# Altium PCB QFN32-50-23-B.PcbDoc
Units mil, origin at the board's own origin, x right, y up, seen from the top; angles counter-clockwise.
Board outline 1000 x 3400 mil, 2 copper layers (Top Layer, Bottom Layer), stack 11.378 mil thick; 33 components, 20 nets, 122 pads, 512 vias.
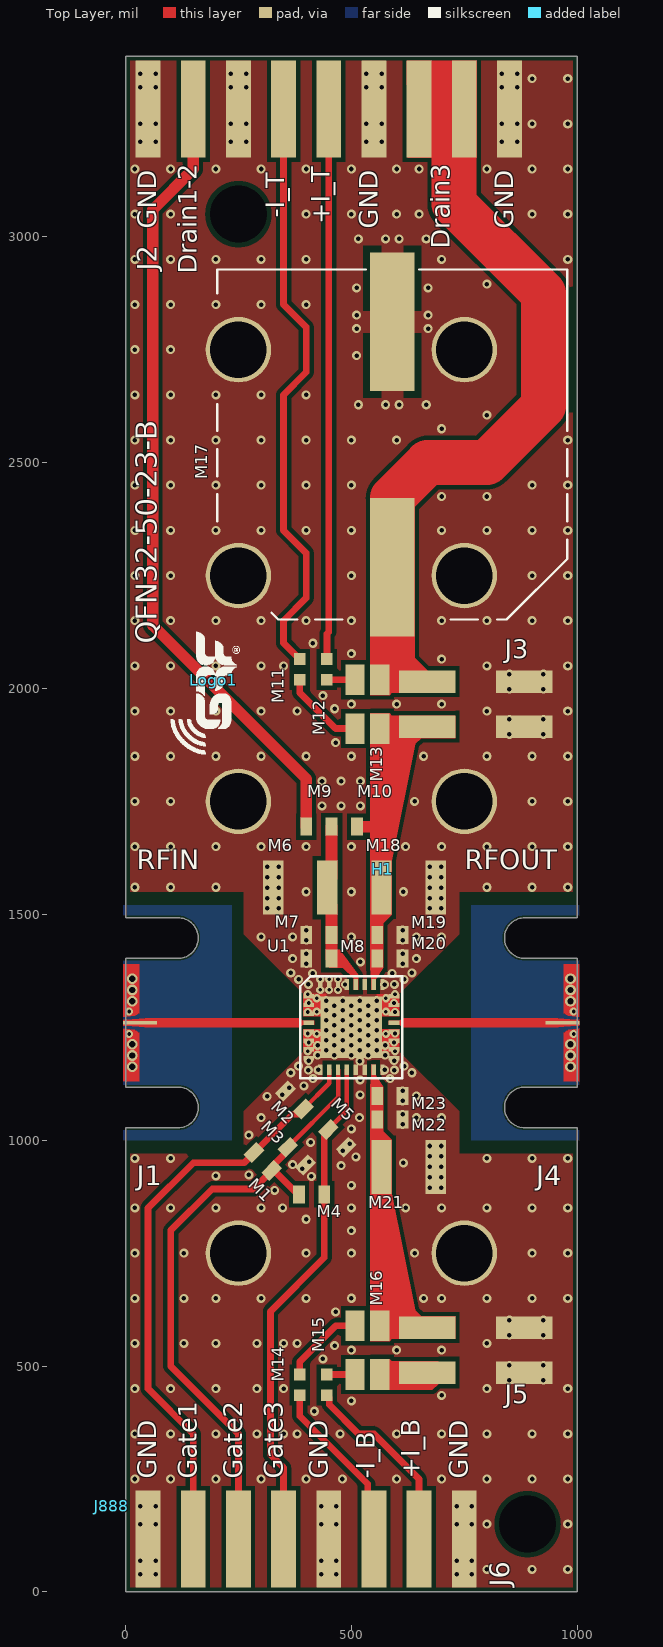
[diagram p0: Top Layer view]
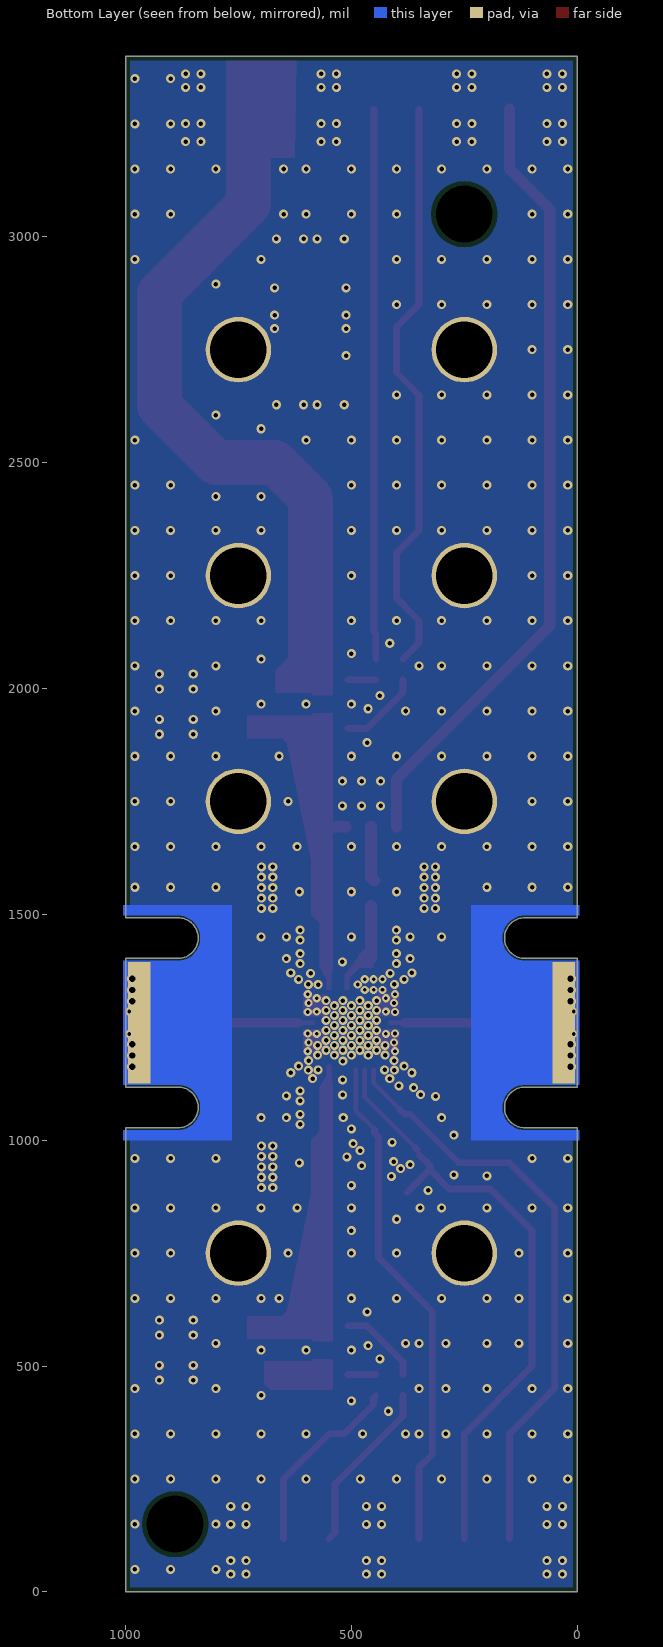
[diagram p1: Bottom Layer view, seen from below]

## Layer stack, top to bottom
Top Layer: signal copper 0.689
Dielectric 1: prepreg 10, RO4350B, Dk 3.48
Bottom Layer: signal copper 0.689

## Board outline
0,0 0,1027.5 116,1027.5 ccw(c116,1072.5) 116,1117.5 0,1117.5 0,1402.5 116,1402.5 ccw(c116,1447.5) 116,1492.5 0,1492.5 0,3400 1000,3400 1000,1492.5 884,1492.5 ccw(c884,1447.5) 884,1402.5 1000,1402.5 1000,1117.5 884,1117.5 ccw(c884,1072.5) 884,1027.5 1000,1027.5 1000,0

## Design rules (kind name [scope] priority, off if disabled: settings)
BackDrilling [IsVia and not InNet('GND')] p1: maxstublength=5 usetopbackdrill=TRUE usebottombackdrill=TRUE holeoversize=10 holetolplus=0.2 holetolminus=0.2
BoardOutlineClearance [All] p1: gap=10 ignorepadtopadclearanceinfootprint=FALSE
Clearance Clearance_I/O [InNetClass('I/O') vs InNet('GND')] p1: gap=7 ignorepadtopadclearanceinfootprint=TRUE
Clearance Clearance_RF_Strip [InNetClass('RF_Strip') vs InNet('GND')] p2: gap=40 ignorepadtopadclearanceinfootprint=TRUE
Clearance Clearance_RF_15-15-8 [InNetClass('RF_15-15-8') vs InNet('GND')] p3: gap=15 ignorepadtopadclearanceinfootprint=TRUE
Clearance Clearance_RF_20-10-12 [InNetClass('RF_20-10-12') vs InNet('GND')] p4: gap=10 ignorepadtopadclearanceinfootprint=TRUE
Clearance Clearance_RF_30-20-16 [InNetClass('RF_30-20-16') vs InNet('GND')] p5: gap=20 ignorepadtopadclearanceinfootprint=TRUE
Clearance Clearance_RF_28-21-16_FR4 [InNetClass('RF_28-21-16_FR4') vs InNet('GND')] p6: gap=21 ignorepadtopadclearanceinfootprint=TRUE
Clearance Clearance_RF_15-27p5-8 [InNetClass('RF_15-27p5-8') vs InNet('GND')] p7: gap=27.5 ignorepadtopadclearanceinfootprint=TRUE
Clearance Clearance_RF_25-22-40_75ohm [InNetClass('RF_25-22-40_75ohm') vs InNet('GND')] p8: gap=22 ignorepadtopadclearanceinfootprint=TRUE
Clearance Clearance_GND [InNet('GND')] p9: gap=10 ignorepadtopadclearanceinfootprint=TRUE
Clearance [All] p10: gap=6 ignorepadtopadclearanceinfootprint=TRUE
ComponentClearance ComponentClearance_Heatsink [InComponent('All') And OnLayer('Top Layer') vs HasFootprint('Heatsink_wFid')] p1: gap=0 collisioncheckmode=3 verticalgap=0 showdistances=FALSE
ComponentClearance ComponentClearance_PCB_Frame [InComponent('All') And OnLayer('Top Layer') vs HasFootprint('PCB_Frame')] p2: gap=0 collisioncheckmode=3 verticalgap=0 showdistances=FALSE
ComponentClearance [All] p3: gap=10 collisioncheckmode=3 verticalgap=10 showdistances=TRUE
HoleSize [All] p1: absolutevalues=TRUE maxlimit=200 minlimit=8 maxpercent=80.000 minpercent=20.000
MinimumSolderMaskSliver [All] p1: minsoldermaskwidth=5
PlaneClearance [Not InNet('GND')] p1: clearance=20
PlaneConnect [InNet('GND')] p1: planeconnectstyle=Direct reliefexpansion=20 reliefentries=4 reliefconductorwidth=10 reliefairgap=10
PolygonConnect [All vs InNet('GND')] p1: connectstyle=Direct reliefconductorwidth=10 reliefentries=4 polygonreliefangle="90 Angle" airgapwidth=10
RoutingVias [All] p1: holewidth=10 width=20 viastyle="Through Hole" minholewidth=8 minwidth=18 maxholewidth=23.62 maxwidth=33.62
SilkToSilkClearance [All] p1: silktosilkclearance=5
SilkToSolderMaskClearance [IsPad] p1: minsilkscreentomaskgap=5 clearancetoexposedcopper=TRUE
SolderMaskExpansion [All] p1: expansion=1 istentingtop=FALSE
UnRoutedNet [All] p1: checkbadconnections=TRUE
Width [All] p1: maxlimit=100 minlimit=6 preferedwidth=10
22 further rules are at their usual default settings.

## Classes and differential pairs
net class RF_Strip: NetJ1_1 NetJ4_1

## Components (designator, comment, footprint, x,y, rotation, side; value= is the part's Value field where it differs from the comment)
H1 "Cooling_Block_Grid" Cooling_Block_Grid 250,1750 r0 top locked
J1 "Clamp_27G_Southwest_RevD" Clamp_27G_Southwest_RevD 0,1260 r0 top
J2 "Header_H_9-Pin_100mil" Header_H_9-Pin_100mil 450,3400 r0 top
J3 "Header_SMD_Dual-2-Pin_100Mil" Header_SMD_Dual-2-Pin_100Mil 775,1965.16 r270 top
J4 "Clamp_27G_Southwest_RevD" Clamp_27G_Southwest_RevD 1000,1260 r180 top
J5 "Header_SMD_Dual-2-Pin_100Mil" Header_SMD_Dual-2-Pin_100Mil 775,535.16 r270 top
J6 "Header_H_8-Pin_100mil" Header_H_8-Pin_100mil 400,0 r180 top
J888 "Comment" PCB_Fab_30T-20G-16D_4003 -30.42,190 r0 top locked
Logo1 "GRF_2021" GRF_2021 195,2018 r90 top
M1 "0603_26x40x30" 0603_26x40x30 303.91,953.14 r135 top (schematic designator M13)
M2 "0603_26x40x30" 0603_26x40x30 374.16,1088.91 r315 top (schematic designator M9)
M3 "0603_26x40x30" 0603_26x40x30 379.07,964.63 r135 top (schematic designator M10)
M4 "0603_26x40x30" 0603_26x40x30 412,880.12 r180 top (schematic designator M14)
M5 "0603_26x40x30" 0603_26x40x30 468.75,1004.31 r135 top (schematic designator M11)
M6 "1210_45x120x75" 1210_45x120x75 386.79,1559.16 r0 top (schematic designator M1)
M7 "0603_26x40x30" 0603_26x40x30 428.29,1454.16 r0 top (schematic designator M2)
M8 "0603_26x40x30" 0603_26x40x30 428.29,1402.16 r0 top (schematic designator M3)
M9 "0603_26x40x30" 0603_26x40x30 428.29,1694 r180 top (schematic designator M7b)
M10 "0603_26x40x30" 0603_26x40x30 484.29,1694 r0 top (schematic designator M7)
M11 "0402_26x26x20" 0402_26x26x20 385.5,2042.16 r270 top (schematic designator M97)
M12 "0402_26x26x20" 0402_26x26x20 445.5,2042.16 r270 top (schematic designator M98)
M13 "Ohmite_LVK12" Ohmite_LVK12 535.5,1965.16 r90 top (schematic designator M99)
M14 "0402_26x26x20" 0402_26x26x20 385.5,458.16 r90 top (schematic designator M18)
M15 "0402_26x26x20" 0402_26x26x20 445.5,458.16 r90 top (schematic designator M21)
M16 "Ohmite_LVK12" Ohmite_LVK12 535.5,535.16 r90 top (schematic designator M20)
M17 "Panasonic_K-Size" Panasonic_K-Size 590.75,2540 r90 top locked (schematic designator M12)
M18 "1210_45x120x75" 1210_45x120x75 626.79,1559.16 r180 top (schematic designator M4)
M19 "0603_26x40x30" 0603_26x40x30 585.29,1454.16 r180 top (schematic designator M5)
M20 "0603_26x40x30" 0603_26x40x30 585.29,1402.16 r180 top (schematic designator M6)
M21 "1210_45x120x75" 1210_45x120x75 626.79,941 r180 top (schematic designator M17)
M22 "0603_26x40x30" 0603_26x40x30 585.29,1046.16 r180 top (schematic designator M16)
M23 "0603_26x40x30" 0603_26x40x30 585.29,1098.16 r180 top (schematic designator M15)
U1 "QFN32_5x5mm_RevA" QFN32_5x5mm_RevA 500,1250.16 r0 top

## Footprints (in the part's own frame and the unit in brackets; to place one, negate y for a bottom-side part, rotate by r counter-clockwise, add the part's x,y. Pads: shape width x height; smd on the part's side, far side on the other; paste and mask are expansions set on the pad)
0402_26x26x20 [mil] "0402 RL (RF Choke)"
  rect 26x26 smd: 1(-23,0) 2(23,0)
0603_26x40x30 [mil] "Generic 0603 SMD"
  rect 26x40 smd: 1(-28,0) 2(28,0)
1210_45x120x75 [mil] "Generic 1210 SMD"
  rect 45x120 smd: 1(-60,0) 2(60,0)
Clamp_27G_Southwest_RevD [mil] "292-04A-6  GaN Microstrip"
  rect 75x8 smd paste-30: 1(32.5,0)
  rect 50x270 smd far side: 2(30,0)
  Bottom Layer region: -5,260 -5,237.5 116,237.5 135.13,233.69 151.36,222.86 162.19,206.63 166,187.5 166,187.5 162.19,168.37 151.36,152.14 135.13,141.31 116,137.5 116,137.5 -5,137.5 -5,-137.5 116,-137.5 135.13,-141.31 151.36,-152.14 162.19,-168.37 166,-187.5 166,-187.5 162.19,-206.63 151.36,-222.86 135.13,-233.69 116,-237.5 116,-237.5 -5,-237.5 -5,-260 235,-260 235,260
Cooling_Block_Grid [mil] "Heatsink Mounting Holes"
  round 145 hole 125 paste-100 mask+20: 1(0,-1000) 1(0,0) 1(0,500) 1(0,1000) 1(500,-1000) 1(500,0) 1(500,1000)
  round 145 hole 125 paste-100 mask+10: 1(500,500)
  round 0 hole 125.98 unplated paste-100 mask+5: 2(0,1300) 2(640,-1600)
GRF_2021 [mil] "2021 GRF Logo"
  silkscreen extent -164,-58 107,95
Header_H_8-Pin_100mil [mil] "Generic Flat Header"
  rect 55x215 smd paste-28: 1(-350,-117.5) 2(-250,-117.5) 3(-150,-117.5) 4(-50,-117.5) 5(50,-117.5) 6(150,-117.5) 7(250,-117.5) 8(350,-117.5)
Header_H_9-Pin_100mil [mil] "Generic Flat Header"
  rect 55x215 smd paste-28: 1(-400,-117.5) 2(-300,-117.5) 3(-200,-117.5) 4(-100,-117.5) 5(0,-117.5) 6(100,-117.5) 7(200,-117.5) 8(300,-117.5) 9(400,-117.5)
Header_SMD_Dual-2-Pin_100Mil [mm] "Generic SMD Header (ex: 95278-801-24LF)"
  rect 1.27x3.18 smd paste-0.711: 1(-1.27,-2.73) 2(-1.27,2.73) 3(1.27,-2.73) 4(1.27,2.73)
Ohmite_LVK12 [mil] "Current Sense Resistor"
  rect 68x43 smd: 1(-54,-27.5) 2(54,-27.5) 3(54,27.5) 4(-54,27.5)
Panasonic_K-Size [mil] "EEV-FK2A221M Capacitor"
  rect 307x98.5 smd: 1(271.65,0) 2(-271.65,0)
  silkscreen extent -387,-387 387,387
PCB_Fab_30T-20G-16D_4003 [mil] "STD RF&Stack  30mil RF 20mil Gap  16mil Dielectric"
QFN32_5x5mm_RevA [mm] "Initial Footprint"
  rect 0.6x0.25 smd paste-100: 1(-2.4,1.75) 2(-2.4,1.25) 3(-2.4,0.75) 4(-2.4,0.25) 5(-2.4,-0.25) 6(-2.4,-0.75) 7(-2.4,-1.25) 8(-2.4,-1.75) 17(2.4,-1.75) 18(2.4,-1.25) 19(2.4,-0.75) 20(2.4,-0.25) 21(2.4,0.25) 22(2.4,0.75) 23(2.4,1.25) 24(2.4,1.75)
  rect 0.25x0.6 smd paste-100: 9(-1.75,-2.4) 10(-1.25,-2.4) 11(-0.75,-2.4) 12(-0.25,-2.4) 13(0.25,-2.4) 14(0.75,-2.4) 15(1.25,-2.4) 16(1.75,-2.4) 25(1.75,2.4) 26(1.25,2.4) 27(0.75,2.4) 28(0.25,2.4) 29(-0.25,2.4) 30(-0.75,2.4) 31(-1.25,2.4) 32(-1.75,2.4)
  rect 3.45x3.45 smd paste-100: 33(0,0)
  silkscreen extent -2.87,-2.87 2.87,2.87

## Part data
H1: library part "Mounting Holes"
J1 J4: library part RF_Conn
J2: library part Header_9-Pin, "Header 9-Pin"
J3 J5: library part Header_Dual-2-Pin, "Header 4-Pin"
J6: library part Header_8-Pin, "Header 8-Pin"
Logo1: library part GRF_Logo, "=CurrentFootprint"
M1 M4 M9 M10 M11 M12 M14 M15: library part Resistor
M2 M3 M5 M6 M7 M8 M18 M19 M20 M21 M22 M23: library part Capacitor
M13 M16: library part Resistor_Ohmite_Current_Sense
M17: library part Capacitor_Panasonic_K
U1: library part QFN32_5x5mm, "QFN32_5x5mm"

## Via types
v1: diameter 20/20 (per signal layer), hole 10, Top Layer to Bottom Layer, 408 vias
v2: diameter 20/20 (per signal layer), hole 10, Top Layer to Bottom Layer, tented top, 63 vias
v3: diameter 18/18 (per signal layer), hole 8, Top Layer to Bottom Layer, 23 vias
v4: diameter 24/24 (per signal layer), hole 14, Top Layer to Bottom Layer, 12 vias
v5: diameter 18/18 (per signal layer), hole 8, Top Layer to Bottom Layer, tented top, 6 vias

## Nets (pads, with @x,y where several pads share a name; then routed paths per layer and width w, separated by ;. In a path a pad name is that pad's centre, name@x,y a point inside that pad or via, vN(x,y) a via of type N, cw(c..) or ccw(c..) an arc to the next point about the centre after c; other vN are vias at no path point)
GND: H1.1 J1.2 J2.1 J2.3 J2.6 J2.9 J3.2 J3.4 J4.2 J5.2 J5.4 J6.1 J6.4 J6.8 M2.1 M3.1 M5.1 M6.1 M7.1 M8.1 M17.1 M18.1 M19.1 M20.1 M21.1 M22.1 M23.1 U1.1 U1.2 U1.3 U1.5 U1.6 U1.7 U1.8 U1.9 U1.13 U1.14 U1.16 U1.17 U1.18 U1.19 U1.20 U1.22 U1.23 U1.24 U1.25 U1.27 U1.29 U1.30 U1.31 U1.32 U1.33
  other v1: 33,39.5 67,39.5 433,39.5 467,39.5 733,39.5 767,39.5 800,50 900,50 979,50 33,69.5 67,69.5 433,69.5 467,69.5 733,69.5 767,69.5 33,149.5 67,149.5 433,149.5 467,149.5 733,149.5 767,149.5 800,150 979,150 33,189.5 67,189.5 433,189.5 467,189.5 733,189.5 767,189.5 21,250 100,250 200,250 300,250 400,250 480,250 600,250 700,250 800,250 900,250 979,250 21,350 100,350 200,350 291,350 380,350 475,350 600,350 700,350 800,350 900,350 979,350 418,400 500,423.16 700,435.16 21,450 100,450 200,450 291,450 350,450.16 800,450 979,450 437,516.16 700,535.16 463,545.16 21,550 129,550 200,550 291,550 350,550 380,550.16 800,550 465,620.16 21,650 129,650 200,650 300,650 400,650 500,650.16 660,650 700,650 800,650 900,650 979,650 21,750 129,750 400,750 500,750 640,750 900,750 979,750 500,800 400,825 21,850 100,850 200,850 300,850 348,850 500,850 620,850 700,850 800,850 900,850 979,850 330,889 674,895 699,895 500,900 674,918 699,918 411.25,920.16 200,921 273,923 674,941 699,941 477.11,943.87 615,950 21,960 100,960 800,960 900,960 979,960 510.12,962.95 674,964.16 699,964.16 674,987.16 699,987.16 410,995.16 273,1011.16 500,1025.16 300,1050.16 518,1050.16 643.79,1050.16 700,1050.16 313.71,1097.26 643.79,1098.16 519.5,1100.16 395,1120.16 365.8,1149.35 634.2,1149.35 426.18,1155.67 573.82,1155.67 405.51,1176.34 594.49,1176.34 443.92,1199.16 481.31,1199.16 518.69,1199.16 556.08,1199.16 462.62,1210.16 500,1210.16 537.38,1210.16 443.92,1221.16 481.31,1221.16 518.69,1221.16 556.08,1221.16 462.62,1232.16 500,1232.16 537.38,1232.16 443.92,1243.16 481.31,1243.16 518.69,1243.16 556.08,1243.16 462.62,1254.16 500,1254.16 537.38,1254.16 443.92,1265.16 481.31,1265.16 518.69,1265.16 556.08,1265.16 462.62,1276.16 500,1276.16 537.38,1276.16 443.92,1287.16 481.31,1287.16 518.69,1287.16 556.08,1287.16 462.62,1298.16 500,1298.16 537.38,1298.16 443.92,1309.16 481.31,1309.16 518.69,1309.16 556.08,1309.16 573.82,1344.65 365.8,1370.65 634.2,1370.65 520,1394.66 369.79,1402.16 643.79,1402.16 300,1450.16 369.79,1450.16 500,1450.16 643.79,1450.16 700,1450.16 314,1513.16 339,1513.16 674,1513.16 699,1513.16 314,1536.16 339,1536.16 674,1536.16 699,1536.16 400,1550 500,1550 615,1550 314,1559.16 339,1559.16 674,1559.16 699,1559.16 21,1560 100,1560 200,1560 800,1560 900,1560 979,1560 314,1582.16 339,1582.16 674,1582.16 699,1582.16 314,1605.16 339,1605.16 674,1605.16 699,1605.16 21,1650 100,1650 200,1650 300,1650 400,1650 500,1650 620,1650 700,1650 800,1650 900,1650 979,1650 435,1740 477.5,1740 520,1740 21,1750 100,1750 640,1750 900,1750 979,1750 435,1795 477.5,1795 520,1795 21,1850 100,1850 200,1850 300,1850 400,1850 500,1850 660,1850 800,1850 900,1850 979,1850 465,1880.16 21,1950 100,1950 300,1950 380,1950.16 800,1950 979,1950 463,1955.16 700,1965.16 437,1984.16 21,2050 100,2050 300,2050 350,2050.16 800,2050 979,2050 700,2065.16 500,2077.16 415,2100.16 21,2150 100,2150 200,2150 300,2150 400,2150 500,2150 700,2150 800,2150 900,2150 979,2150 21,2250 100,2250 500,2250 900,2250 979,2250 21,2350 100,2350 200,2350 300,2350 400,2350 500,2350 700,2350 800,2350 900,2350 979,2350 700,2425 800,2425 21,2450 100,2450 200,2450 300,2450 400,2450 500,2450 900,2450 979,2450 21,2550 100,2550 200,2550 300,2550 400,2550 500,2550 600,2550 979,2550 700,2575 800,2605 515.75,2628.11 575.75,2628.11 605.75,2628.11 665.75,2628.11 21,2650 100,2650 200,2650 300,2650 400,2650 511.54,2736.65 21,2750 100,2750 511.54,2796.65 669.96,2796.65 511.54,2826.65 669.96,2826.65 21,2850 100,2850 200,2850 300,2850 400,2850 511.54,2886.65 669.96,2886.65 800,2895 21,2950 100,2950 200,2950 300,2950 400,2950 700,2950 979,2950 515.75,2995.2 575.75,2995.2 605.75,2995.2 665.75,2995.2 21,3050 100,3050 400,3050 500,3050 600,3050 650,3050 900,3050 979,3050 21,3150 100,3150 200,3150 300,3150 400,3150 500,3150 600,3150 650,3150 800,3150 900,3150 979,3150 33,3210.5 67,3210.5 233,3210.5 267,3210.5 533,3210.5 567,3210.5 833,3210.5 867,3210.5 900,3250 979,3250 33,3250.5 67,3250.5 233,3250.5 267,3250.5 533,3250.5 567,3250.5 833,3250.5 867,3250.5 33,3330.5 67,3330.5 233,3330.5 267,3330.5 533,3330.5 567,3330.5 833,3330.5 867,3330.5 900,3350 979,3350 33,3360.5 67,3360.5 233,3360.5 267,3360.5 533,3360.5 567,3360.5 833,3360.5 867,3360.5
  other v2: 350,350 850,468.66 925,468.66 850,501.66 925,501.66 500,535.16 600,535.16 850,568.66 925,568.66 850,601.66 925,601.66 391.09,937.05 370,946.16 406.64,952.61 480.77,976.74 496.33,992.29 613.29,1035.16 613.29,1057.16 613.29,1087.16 346.58,1100.93 613.29,1109.16 362.14,1116.49 519.5,1133.66 415,1136.16 586,1136.16 405,1155.16 595,1155.16 383,1163.84 617,1163.84 518.69,1175.16 425.23,1188.16 462.62,1188.16 500,1188.16 537.38,1188.16 574.77,1188.16 425.23,1210.16 574.77,1210.16 405,1345.16 595,1345.16 383,1356.16 617,1356.16 414,1369.16 590,1369.16 400.29,1391.16 613.29,1391.16 400.29,1413.16 613.29,1413.16 400.29,1443.16 613.29,1443.16 400.29,1465.16 613.29,1465.16 850,1898.66 925,1898.66 850,1931.66 925,1931.66 200,1950 500,1965.16 600,1965.16 850,1998.66 925,1998.66 850,2031.66 925,2031.66 200,2050
  other v3: 403.51,1197.02 596.49,1197.02 405.51,1216.21 594.49,1216.21 8,1235 992,1235 403.5,1236.14 596.5,1236.14 403.5,1283.86 596.5,1283.86 8,1285 992,1285 405.51,1303.79 594.49,1303.79 403.51,1322.98 596.49,1322.98 431.1,1332.84 450.79,1332.84 470.47,1332.84 486,1344.65 431.1,1356.46 450.79,1356.46 470.47,1356.46
  other v4: 15,1162.5 985,1162.5 15,1187.5 985,1187.5 15,1212.5 985,1212.5 15,1307.5 985,1307.5 15,1332.5 985,1332.5 15,1357.5 985,1357.5
  other v5: 423.5,1235.39 576.5,1235.39 423.5,1284.61 576.5,1284.61 423.5,1314.13 576.5,1314.13
NetJ1_1: J1.1 U1.4 | length 327
  Top Layer w20: J1.1@45,1260 372,1260
NetJ2_2: J2.2 M9.2 | length 1766.3
  Top Layer w25: J2.2 150,3150 60.5,3060.5 60.5,2139.5 400.29,1799.71 M9.2
NetJ2_4: J2.4 M11.1 | length 1315
  Top Layer w15: J2.4 350,2850 400,2800 400,2700 350,2650 350,2350 400,2300 400,2200 350,2150 350,2100.5 M11.1@385.5,2065
NetJ2_5: J2.5 M12.1 | length 1218.6
  Top Layer w15: M12.1@446.01,2065.51 446.01,2121.01 450,2125 J2.5
NetJ2_7: J2.7 J2.8 J3.1 M13.2 M17.2 | length 1203.7
  Top Layer w98.5: M17.2 590.75,2421.85
  Top Layer w99: 590.75,2421.85 668.9,2500
  Top Layer w100: 668.9,2500 800,2500 925,2625 925,2750 925,2875 727.5,3072.5 J2.8@727.5,3175
NetJ3_3: J3.3 M10.2 M13.1 M18.2 M19.2 M20.2 U1.26 | length 195.9
  Top Layer w26: M10.2 557.29,1694 ; M20.2 M19.2 M18.2@557.29,1509.16 ; M18.2@557.29,1519.16 566.79,1528.66 M18.2
NetJ4_1: J4.1 U1.21 | length 327
  Top Layer w20: 628,1260 J4.1@955,1260
NetJ5_1: J5.1 M16.2 M21.2 M22.2 M23.2 U1.15 | length 107
  Top Layer w26: M21.2@557.29,991.16 M23.2
NetJ5_3: J5.3 M16.1
NetJ6_2: J6.2 M15.1 | length 421.4
  Top Layer w15: M15.1@446.01,434.49 451,429.5 451,415 516,350 550,350 650,250 J6.2
NetJ6_3: J6.3 M14.1 | length 385.6
  Top Layer w15: M14.1@385.5,435 385.71,434.79 385.71,389.29 536.29,238.71 536.29,131.21 J6.3
NetJ6_5: J6.5 M4.1 M5.2 U1.12 | length 1120.1
  Top Layer w10: M5.2 490.16,1065.32 U1.12
  Top Layer w15: J6.5 350,275 321,304 321,621 440,740 440,879.96 M5.2@440,1007.22 ; M5.2@440,1007.38 448.95,1016.33 M5.2
NetJ6_6: J6.6 M1.1 M3.2 M4.2 U1.11 | length 1360.3
  Top Layer w10: M3.2 470.47,1095.63 U1.11
  Top Layer w15: J6.6 250,350 100,500 100,800 192,892 283.53,892 326.21,934.68 M1.1@326.21,941.07 ; M1.1@326.21,934.84 M4.2@376.18,884.87 ; M1.1@326.21,943.59 M3.2@349.01,966.39 ; M3.2@354.32,979.48 M3.2
NetJ6_7: J6.7 M1.2 M2.2 U1.10 | length 1318.7
  Top Layer w10: M2.2 450.79,1125.95 U1.10
  Top Layer w15: J6.7 150,350 50,450 50,850 150,950 262.33,950 M1.2@286.61,974.28 ; M1.2@286.61,974.44 369.61,1057.44 382.28,1057.44 M2.2
NetM6_2: M6.2 M7.2 M8.2 M9.1 M10.1 U1.28 | length 238.6
  Top Layer w26: M6.2@450,1575.16 M6.2@456.29,1581.45 ; M8.2 456.29,1512.16 M6.2@456.29,1519.16 ; M6.2@456.29,1581.29 M9.1
NetM11_2: M11.2 M13.4 | length 183.7
  Top Layer w15: M11.2 385.5,1990.99 465.33,1911.16 M13.4
NetM12_2: M12.2 M13.3 | length 62.5
  Top Layer w15: M12.2 M13.3
NetM14_2: M14.2 M16.3 | length 183.7
  Top Layer w15: M14.2 385.5,509.33 465.33,589.16 M16.3
NetM15_2: M15.2 M16.4 | length 62.5
  Top Layer w15: M15.2 M16.4
pads on no net: H1.2

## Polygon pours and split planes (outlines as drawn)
GND on Bottom Layer "GND_L02_P001" (solid, pour order 1): 1000,0 1000,3400 0,3400 0,0
GND on Top Layer "GND_L01_P000" (solid, pour order 0): 1000,0 1000,3400 0,3400 0,0

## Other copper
Top Layer:
  region net GND: 1005,1273 1000,1273 980,1275.5 970,1281.57 970,1390 1005,1390
  region net GND: 1005,1247 1000,1247 980,1244.5 970,1238.43 970,1130 1005,1130
  region net NetJ4_1: 1005,1267 1000,1267 955,1270 945,1270 945,1250 955,1250 1000,1253 1005,1253
  region net GND: -5,1273 0,1273 20,1275.5 30,1281.57 30,1390 -5,1390
  region net GND: -5,1247 0,1247 20,1244.5 30,1238.43 30,1130 -5,1130
  region net NetJ1_1: -5,1267 0,1267 45,1270 55,1270 55,1250 45,1250 0,1253 -5,1253
  region net NetJ4_1: 628,1270 615,1270 606.3,1264.92 582.68,1264.92 582.68,1255.08 606.3,1255.08 615,1250 628,1250
  region net NetJ1_1: 372,1270 385,1270 393.7,1264.92 417.32,1264.92 417.32,1255.08 393.7,1255.08 385,1250 372,1250
  pour cut-out: 290.62,924 279.66,934.96 382.67,1037.97 393.63,1027.01
  region net GND: 606.3,1322.84 606.3,1274.76 556.08,1274.76 556.08,1322.84
  region net GND: 606.3,1196.02 606.3,1245.24 556.08,1245.24 556.08,1196.02
  region net GND: 393.7,1196.02 393.7,1245.24 443.92,1245.24 443.92,1196.02
  region net GND: 393.7,1323.98 393.7,1274.76 443.92,1274.76 443.92,1323.98
  pour cut-out: 738.73,1550 738.73,1456.4 606.3,1323.98 606.3,1196.02 738.73,1063.6 738.73,970 1000,970 1000,1550
  pour cut-out: 261.27,1550 261.27,1456.4 393.7,1323.98 393.7,1196.02 261.27,1063.6 261.27,970 0,970 0,1550
  region net NetJ5_1: 541.5,1118.16 544.29,1143.86 544.29,1167.48 554.13,1167.48 554.13,1143.86 570.29,1118.16 570.29,1020.16 589.29,1001.16 589.29,881.16 641.5,623.16 654.5,610.16 730.12,610.16 730.12,560.16 589.5,560.16 584.5,555.16 541.5,555.16
  region net NetJ3_3: 541.5,1382.16 544.29,1356.46 544.29,1332.84 554.13,1332.84 554.13,1356.46 570.29,1382.16 570.29,1480.16 589.29,1499.16 589.29,1619.16 641.5,1877.16 654.5,1890.16 730.12,1890.16 730.12,1940.16 589.5,1940.16 584.5,1945.16 541.5,1945.16
  region net NetJ5_3: 692.52,460.16 679.52,447.16 541.5,447.16 541.5,515.16 584.5,515.16 589.5,510.16 692.52,510.16
  region net NetJ2_7: 541.5,1985.16 541.5,2422 640,2422 640,2067.68 667.52,2040.16 667.52,1990.16 589.5,1990.16 584.5,1985.16
  region net NetJ2_7: 622.5,3390 777.5,3390 777.5,3175 625,3175
  region net NetM6_2: 504.92,1332.84 504.92,1358.24 481,1382.16 451.06,1382.16 451.06,1422.16 473.85,1422.16 514.76,1366.06 514.76,1332.84

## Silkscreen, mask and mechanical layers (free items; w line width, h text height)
Top Overlay:
  lines w5: 203.3,2370 203.3,2430 ; 203.3,2470 203.3,2530 ; 203.3,2570 203.3,2630 ; 323.24,2167.4 338.09,2152.55 380,2152.55 ; 420,2152.55 480,2152.55 ; 720,2152.55 780,2152.55 ; 978.2,2287.34 978.2,2330 ; 978.2,2370 978.2,2430 ; 978.2,2470 978.2,2530
  text "-I_T" at 366.2,3041.78 h70 r90
  text "+I_T" at 466.2,3027.53 h70 r90
  text "GND" at 82.42,3017.42 h70 r90
  text "GND" at 572.42,3017.42 h70 r90
  text "GND" at 872.42,3017.42 h70 r90
  text "Drain3" at 732.13,2973.1 h70 r90
  text "Drain1-2" at 172.16,2917.82 h70 r90
  text "QFN32-50-23-B" at 84.55,2098.88 h80 r90
  text "RFIN" at 25,1585.83 h75
  text "RFOUT" at 750.56,1585.83 h75
  text "GND" at 82.42,250 h70 r90
  text "Gate1" at 172.42,250 h70 r90
  text "Gate2" at 272.42,250 h70 r90
  text "Gate3" at 362.42,250 h70 r90
  text "GND" at 462.42,250 h70 r90
  text "-I_B" at 566.2,250 h70 r90
  text "+I_B" at 666.2,250 h70 r90
  text "GND" at 772.42,250 h70 r90
Top Solder:
  region: 1000,1550 738.73,1550 738.73,1456.4 606.3,1323.98 606.3,1196.02 738.73,1063.6 738.73,970 1000,970
  region: 0,1550 261.27,1550 261.27,1456.4 393.7,1323.98 393.7,1196.02 261.27,1063.6 261.27,970 0,970
Board_Dimension:
  lines w10: 0,1027.5 0,0 1000,0 1000,1027.5 ; 0,1117.5 0,1402.5 ; 0,1492.5 0,3400 1000,3400 1000,1492.5 ; 1000,1117.5 1000,1402.5
Drill Drawing:
  lines w15: -1475.37,-2635 3609.24,-2635 ; -1475.37,-1885 3609.24,-1885 ; -924.49,-2785 -924.49,-1735 ; -324.65,-2785 -324.65,-1735 ; 825.01,-2785 825.01,-1735 ; 1330.89,-2785 1330.89,-1735 ; 2064.69,-2785 2064.69,-1735 ; -1475.37,-2785 3609.24,-2785 3609.24,-1735 -1475.37,-1735 -1475.37,-2785
  text "Symbol" at -1385.37,-1840 h72
  text "Count" at -879.49,-1840 h72
  text "Hole Size" at -279.65,-1840 h72
  text "Plated" at 870.01,-1840 h72
  text "Hole Type" at 1375.89,-1840 h72
  text "Drill Layer Pair" at 2109.69,-1840 h72
  text "29" at -879.49,-1990 h60
  text "8.00mil (0.203mm)" at -279.65,-1990 h60
  text "PTH" at 870.01,-1990 h60
  text "Round" at 1375.89,-1990 h60
  text "Top Layer - Bottom Layer" at 2109.69,-1990 h60
  text "A" at -1414.46,-1999.99 h66.67
  text "471" at -879.49,-2140 h60
  text "10.00mil (0.254mm)" at -279.65,-2140 h60
  text "PTH" at 870.01,-2140 h60
  text "Round" at 1375.89,-2140 h60
  text "Top Layer - Bottom Layer" at 2109.69,-2140 h60
  text "B" at -1414.46,-2149.99 h66.67
  text "12" at -879.49,-2290 h60
  text "14.00mil (0.356mm)" at -279.65,-2290 h60
  text "PTH" at 870.01,-2290 h60
  text "Round" at 1375.89,-2290 h60
  text "Top Layer - Bottom Layer" at 2109.69,-2290 h60
  text "W" at -1414.46,-2299.99 h66.67
  text "8" at -879.49,-2440 h60
  text "125.00mil (3.175mm)" at -279.65,-2440 h60
  text "PTH" at 870.01,-2440 h60
  text "Round" at 1375.89,-2440 h60
  text "Top Layer - Bottom Layer" at 2109.69,-2440 h60
  text "H" at -1414.46,-2449.99 h66.67
  text "2" at -879.49,-2590 h60
  text "125.98mil (3.200mm)" at -279.65,-2590 h60
  text "NPTH" at 870.01,-2590 h60
  text "Round" at 1375.89,-2590 h60
  text "Top Layer - Bottom Layer" at 2109.69,-2590 h60
  text "N" at -1414.46,-2599.99 h66.67
  text "522 Total" at -879.49,-2740 h60
Document:
  lines w10: -407,807.93 -57,1268 ; -32,1012.23 -57,1012.23 -57,1512.23 -32,1512.23 ; 153.49,1259.48 1236,1895 763.99,1259.84 ; 534,2559.06 1254,2690 ; 1045,999.55 1070,999.55 1070,1499.55 1045,1499.55 ; 1070,1253.84 1320,803.84 ; 334,2244 534,2244 534,2844 334,2844 334,2244
  text "Note A" at 1257,1853.27 h125

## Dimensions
1000,0 to 1000,3400 on Mechanical 16
0,0 to 1000,0 on Mechanical 16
